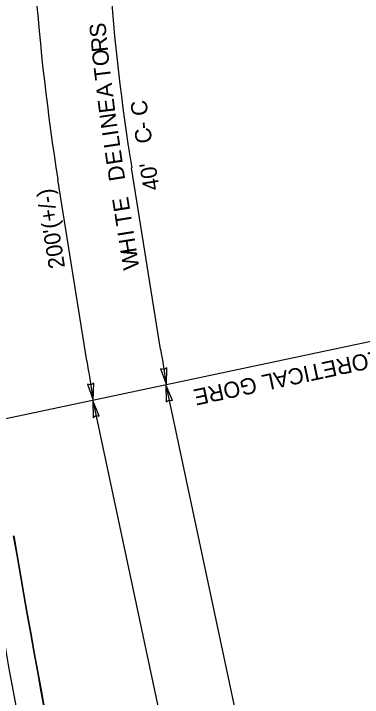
# Model space of a CAD drawing. Extents: x 578088 to 579220, y 1508751 to 1510400.
# Drawn here: x 578695 to 578845.7, y 1509092.1 to 1509387.9 of the extents above; entities that cross this region are included whole.
import ezdxf

# ---------------------------------------------------------------- set-up
doc = ezdxf.new("R2010")
doc.units = 0
for name, color, linetype in [('1', 7, 'Continuous'), ('18', 7, 'Continuous'), ('41', 7, 'Continuous'), ('52', 7, 'Continuous')]:
    doc.layers.add(name, color=color, linetype=linetype)

msp = doc.modelspace()

# ---------------------------------------------------------------- linework, layer by layer
at = {"layer": '1'}
for p, q in [((578759.9, 1509233.97), (578758.47, 1509234.29)), ((578758.47, 1509234.29), (578760.97, 1509227.35)), ((578761.19, 1509234.74), (578759.9, 1509233.97)), ((578760.97, 1509227.35), (578761.19, 1509234.74)), ((578728.31, 1509227.26), (578726.89, 1509227.58)), ((578726.89, 1509227.58), (578729.39, 1509220.64)), ((578729.61, 1509228.02), (578728.31, 1509227.26)), ((578729.39, 1509220.64), (578729.61, 1509228.02)), ((578760.74, 1509227.31), (578760.88, 1509219.92)), ((578763.57, 1509220.49), (578760.74, 1509227.31)), ((578729.16, 1509220.59), (578729.3, 1509213.21)), ((578731.99, 1509213.78), (578729.16, 1509220.59)), ((578760.88, 1509219.92), (578762.13, 1509220.75)), ((578762.13, 1509220.75), (578763.57, 1509220.49)), ((578729.3, 1509213.21), (578730.55, 1509214.04)), ((578730.55, 1509214.04), (578731.99, 1509213.78))]:
    msp.add_line(p, q, dxfattribs=at)
at = {"layer": '18'}
for radius, start, end in [(5729.75, 189.730019, 192.46846), (5741.58, 189.73613, 192.235242)]:
    msp.add_arc((584342.13, 1510130.3), radius, start, end, dxfattribs=at)
at = {"layer": '41'}
msp.add_arc((584342.13, 1510130.3), 5729.58, 189.72994, 192.46846, dxfattribs=at)
msp.add_arc((584342.13, 1510130.3), 5729.58, 189.72994, 192.46846, dxfattribs=at)
msp.add_arc((584342.13, 1510130.3), 5729.58, 189.72994, 192.46846, dxfattribs=at)
at = {"layer": '52'}
for p, q in [((578758.49, 1509242.76), (578745.97, 1509321.25)), ((578726.61, 1509237.68), (578714.1, 1509316.17)), ((578869.57, 1509250.44), (578689.51, 1509212.17)), ((578760.74, 1509227.31), (578832.01, 1508892)), ((578729.16, 1509220.59), (578791.66, 1508926.54))]:
    msp.add_line(p, q, dxfattribs=at)
for centre, radius, start, end in [((579703.85, 1509473.98), 969.97, 184.12715, 189.05927), ((579703.85, 1509473.98), 1002.26, 184.12715, 189.05927), ((584416.6, 1510144.89), 5729.58, 189.05897, 189.21503), ((584416.6, 1510144.89), 5761.86, 189.05897, 189.21503)]:
    msp.add_arc(centre, radius, start, end, dxfattribs=at)

# ---------------------------------------------------------------- texts
for s, rotation, p in [('S', 95.6175, (578735.19, 1509378.03)), ('R', 95.6175, (578735.82, 1509371.6)), ('O', 95.6175, (578736.41, 1509365.57)), ('T', 96.9942, (578737.18, 1509359.62)), ('A', 96.9942, (578738.12, 1509351.98)), ('E', 96.9942, (578738.93, 1509345.32)), ('C', 96.9942, (578753.18, 1509344.13)), ('N', 98.3709, (578739.87, 1509338.73)), ('C', 98.3709, (578754.96, 1509332.29)), ('-', 94.9568, (578754.08, 1509338.27)), ('I', 98.3709, (578740.35, 1509335.45)), ('L', 98.3709, (578741.11, 1509330.26)), ('E', 98.3709, (578742.17, 1509323.09)), ('D', 99.0591, (578743.26, 1509316.08)), ("40'", 99.0591, (578758.09, 1509311.94)), ("200'(+/-)", 99.0591, (578717.2, 1509278.21)), ('E', 99.0591, (578745.37, 1509302.8)), ('T', 99.0591, (578746.33, 1509296.79)), ('I', 99.0591, (578747.07, 1509292.18)), ('H', 99.0591, (578748.25, 1509284.76)), ('W', 99.0591, (578749.37, 1509277.71)), ('THEORETICAL GORE', 192, (578865.85, 1509245.07))]:
    msp.add_text(s, height=7, rotation=rotation, dxfattribs=at).set_placement(p)

doc.saveas('drawing.dxf')
